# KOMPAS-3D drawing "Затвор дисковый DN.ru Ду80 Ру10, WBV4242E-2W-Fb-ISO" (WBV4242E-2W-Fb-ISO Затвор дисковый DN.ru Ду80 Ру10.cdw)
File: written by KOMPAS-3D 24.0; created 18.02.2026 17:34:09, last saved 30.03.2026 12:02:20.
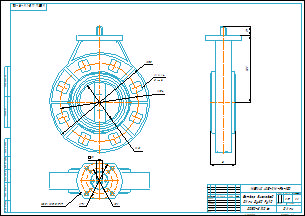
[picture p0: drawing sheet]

Document properties: Автор: R2D2; Форматы листов документа: A2; Полное имя файла: WBV4242E-2W-Fb-ISO Затвор дисковый DN.ru Ду80 Ру10.m3d; Масса: 1.37; Наименование: Затвор дисковый DN.ru Ду80 Ру10; Количество листов документа: 1; Примечание: D050-81206

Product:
- Part/product: Затвор дисковый DN.ru Ду80 Ру10  | designation WBV4242E-2W-Fb-ISO
    Масса: 1.37
    Раздел спецификации: Прочие изделия
    Форматы листов документа: A2
    Примечание: D050-81206

Views: Вид 1, Спереди, Проекционный вид 2, Проекционный вид 3
Referenced files in E:\Работа\Зайцев\WBV4242E-2W-Fb-ISO Затвор дисковый DN.ru Ду50-200 Ру10\DN80\: WBV4242E-2W-Fb-ISO Затвор дисковый DN.ru Ду80 Ру10.m3d
Referenced files in E:\Работа\Зайцев\Для компаса\: чертеж DN.ru А3.cdt
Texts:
  WBV4242E-2W-Fb-ISO
  ISO 5211 F05/F07
  чертеж DN.ru А3.cdt
  Затвор дисковый
  DN.ru Ду80 Ру10
  Затвор дисковый DN.ru Ду80 Ру10
  WBV4242E-2W-Fb-ISO Затвор дисковый DN.ru Ду80 Ру10
Dimensions and other numbers on the sheet: 0; 3; 2; 4; 195; 154; 8 отв.; 80; 48; 131; 17; 70; 50; 11; 1:1; 1; 1,37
